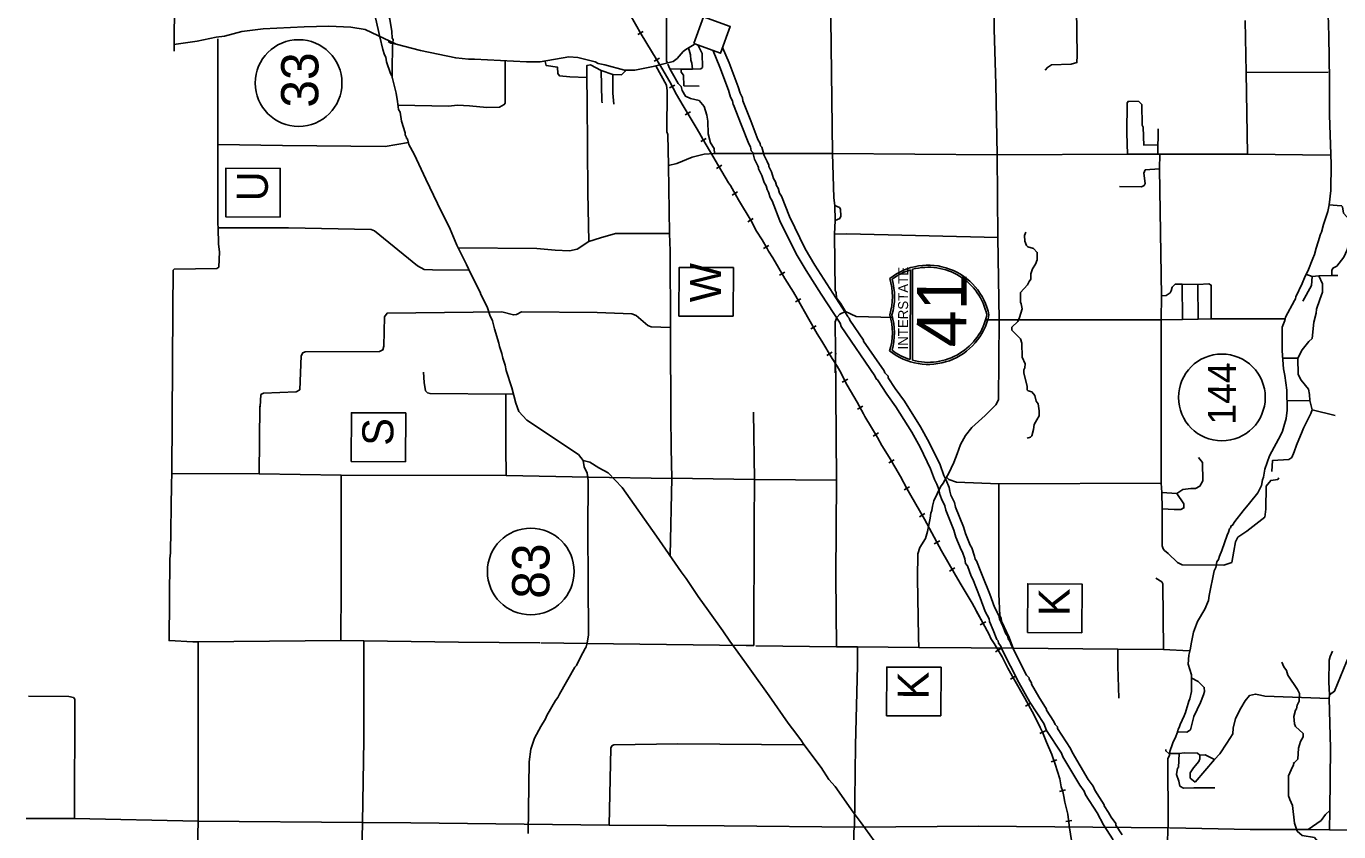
# Model space of a CAD drawing. Extents: x 299354 to 1325680, y 96128 to 228242.
# Drawn here: x 299553 to 341858, y 158651 to 184619 of the extents above; entities that cross this region are included whole.
import ezdxf

# ---------------------------------------------------------------- set-up
doc = ezdxf.new("R2010")
doc.units = 0
for name, color, linetype in [('Level 12', 7, 'Continuous'), ('Level 13', 7, 'Continuous'), ('Level 2', 7, 'Continuous'), ('Level 4', 7, 'Continuous'), ('Level 57', 7, 'Continuous')]:
    doc.layers.add(name, color=color, linetype=linetype)

msp = doc.modelspace()

# ---------------------------------------------------------------- linework, layer by layer
at = {"layer": 'Level 12'}
for p, q in [((308332, 182788), (308332, 182788)), ((328055, 176764), (328047, 173872)), ((328114, 173853), (328122, 176783)), ((338091, 172653), (338091, 172653)), ((315815, 167041), (315815, 167041))]:
    msp.add_line(p, q, dxfattribs=at)
for centre in [(308332, 182788), (338091, 172653), (315815, 167041)]:
    msp.add_circle(centre, 1398, dxfattribs=at)
for centre, radius, start, end in [((328624, 174917), 1999, 11.3832, 128.1773), ((328624, 174917), 1933, 11.7868, 105.0434), ((325474, 175909), 1999, 342.8553, 16.8422), ((325474, 175909), 2066, 343.4192, 15.5586), ((328624, 174917), 1933, 107.1012, 126.8422), ((328626, 175717), 1999, 231.5152, 348.3093), ((325471, 174741), 1999, 342.8502, 16.8372), ((325471, 174741), 2066, 344.1339, 16.2733), ((328626, 175717), 1933, 254.649, 347.9057), ((328626, 175717), 1933, 232.8503, 252.5912)]:
    msp.add_arc(centre, radius, start, end, dxfattribs=at)
at = {"layer": 'Level 13'}
for p, q in [((306839, 179290), (306839, 179290)), ((321447, 176091), (321447, 176091)), ((310886, 171402), (310886, 171402)), ((332686, 165889), (332686, 165889)), ((328138, 163206), (328138, 163206))]:
    msp.add_line(p, q, dxfattribs=at)
for points in [[(307733, 178468), (305983, 178475), (305989, 180045), (307739, 180038)], [(322341, 175269), (320591, 175276), (320598, 176846), (322348, 176839)], [(311779, 170581), (310030, 170588), (310036, 172158), (311786, 172151)], [(333580, 165068), (331830, 165075), (331836, 166645), (333586, 166638)], [(329032, 162384), (327282, 162391), (327288, 163961), (329038, 163954)]]:
    msp.add_lwpolyline(points, close=True, dxfattribs=at)
at = {"layer": 'Level 2'}
for points in [[(310952, 184277), (310809, 184886), (310825, 185331), (310839, 185723), (310854, 186115), (310836, 186444), (310724, 186774), (310602, 187115), (310416, 187509), (310199, 187873), (309795, 188471), (308893, 189723), (308168, 190760), (307672, 191603), (307050, 192523), (306648, 193301), (306143, 194262), (305698, 195020), (304423, 196414)], [(320131, 191177), (320151, 189785), (320164, 187519), (320191, 186852), (320193, 183502), (320223, 183429)], [(336322, 158097), (336363, 158913), (336349, 161013), (336400, 161113), (336417, 161237), (336503, 161487), (336520, 161553), (336588, 161669), (336657, 161860), (336683, 161960), (336717, 162010), (336751, 162109), (336870, 162383), (336921, 162500), (336938, 162566), (337007, 162782), (337025, 162857), (337059, 162940), (337111, 163173), (337116, 163715), (337002, 164057), (337022, 164340), (337073, 164515), (337109, 164765), (337179, 165089), (337307, 165430), (337544, 165827), (337663, 166101), (337682, 166268), (337847, 167066), (337898, 167166), (337933, 167349), (337984, 167432), (338019, 167540), (338087, 167723), (338258, 168213), (338309, 168312), (338335, 168412), (338369, 168445), (338386, 168511), (338436, 168536), (338504, 168652), (338774, 169000), (338985, 169239), (339255, 169579), (339366, 169811), (339401, 169994), (339435, 170085), (339470, 170335), (339625, 170775), (339989, 171447), (340041, 171563), (340092, 171721), (340161, 171971), (340197, 172245), (340186, 172887), (340124, 173363), (340076, 173580), (340031, 174155), (340038, 174922), (340124, 175138), (340141, 175237), (340430, 175777), (340464, 175835), (340473, 175901), (340677, 176324), (340779, 176557), (340864, 176723), (341026, 177130), (341077, 177262), (341129, 177470), (341198, 177670), (341267, 177911), (341301, 177977), (341370, 178226), (341421, 178384), (341507, 178650), (341551, 178866), (341605, 179324), (341613, 180174), (341561, 181750), (341563, 182883), (341543, 184308), (341516, 185000)], [(311475, 184039), (310479, 184518), (310017, 184588), (309302, 184617), (308513, 184605), (307187, 184536), (306502, 184449), (305943, 184297), (305679, 184268), (305057, 184137), (304309, 184030)], [(305728, 184209), (305732, 180807)], [(310952, 184277), (311048, 183868), (311096, 183701), (311146, 183617), (311161, 183467), (311291, 183091), (311340, 183023), (311477, 182464), (311524, 182188), (311555, 181938), (311605, 181854), (311652, 181562), (311765, 181186), (311765, 181119), (311814, 181036), (311814, 181002), (311839, 180985), (311887, 180802), (312051, 180492), (312435, 179688), (312812, 178910), (313213, 178073), (313433, 177563), (313744, 176935), (313883, 176634), (314195, 176022), (314194, 175997), (314358, 175679), (314415, 175545), (314497, 175303), (314578, 175119), (314643, 174860), (314789, 174400), (314804, 174300), (314886, 174066), (314909, 173924), (314990, 173690), (315022, 173523), (315201, 172963), (315329, 172470), (315435, 172194), (315683, 171925), (317349, 170810), (317506, 170617)], [(311217, 184125), (311300, 184074), (311475, 184039), (312265, 183840), (313397, 183596), (313806, 183559), (313997, 183558), (315673, 183476), (315840, 183474), (316115, 183472), (317042, 183630), (317334, 183611), (317891, 183472), (317991, 183422), (318199, 183370), (318840, 183206), (319165, 183203), (319758, 183322), (320402, 183483), (320536, 183582), (320730, 183805), (320814, 183871), (321082, 184035), (321106, 184048)], [(321697, 183825), (321911, 183297), (322189, 182563), (322256, 182338), (322317, 182213), (322337, 182094), (322349, 182081), (322598, 181452), (322839, 180831), (322896, 180729), (322915, 180606), (322971, 180549), (323028, 180333), (323134, 180118), (323158, 180069), (323157, 180027), (323266, 179804), (323333, 179579), (323398, 179472), (323430, 179356), (323480, 179271), (323530, 179100), (323599, 178994), (323848, 178351), (324370, 177284), (324687, 176748), (325174, 175982), (325787, 175044), (325820, 174944), (326909, 173353), (326949, 173252), (326988, 173215), (327290, 172759), (327585, 172349), (328098, 171536), (328364, 171050), (328702, 170351), (328825, 170004), (328908, 169852), (328979, 169662), (328994, 169558), (329051, 169383), (329162, 169155), (329193, 169020), (329447, 168371), (329512, 168152), (329683, 167740), (329730, 167661), (329802, 167445), (329831, 167302), (329889, 167224), (330014, 166895), (330064, 166793), (330305, 166191), (330462, 165757), (330586, 165520), (330601, 165425), (330722, 165150), (330839, 164846), (330878, 164806), (330892, 164732), (330966, 164638), (331009, 164519), (331543, 163464), (331546, 163459), (331905, 162833), (332350, 162137), (332443, 161914), (332919, 161182), (332966, 161068), (333509, 160156), (333651, 159956), (333698, 159842), (334075, 159260), (334272, 158877), (334588, 158388)], [(321999, 183931), (322210, 183439), (322502, 182668), (322564, 182458), (322634, 182316), (322651, 182215), (322906, 181572), (323138, 180972), (323212, 180839), (323224, 180762), (323267, 180718), (323339, 180449), (323430, 180263), (323488, 180144), (323488, 180102), (323575, 179924), (323638, 179714), (323704, 179604), (323737, 179486), (323785, 179403), (323833, 179240), (323895, 179145), (324151, 178483), (324661, 177441), (324968, 176921), (325451, 176161), (326037, 175265), (326037, 175250), (326082, 175204), (326103, 175139), (326539, 174504), (326538, 174471), (326887, 173969), (327203, 173508), (327228, 173443), (327337, 173343), (327336, 173287), (327562, 172946), (327859, 172534), (328382, 171704), (328658, 171202), (329007, 170478), (329128, 170139), (329209, 169990), (329301, 169745), (329317, 169633), (329358, 169507), (329475, 169265), (329509, 169117), (329760, 168478), (329824, 168262), (329979, 167888), (330032, 167799), (330121, 167531), (330140, 167439), (330181, 167383), (330317, 167027), (330365, 166927), (330613, 166309), (330765, 165890), (330903, 165625), (330920, 165519), (331027, 165276), (331122, 165028), (331183, 164966), (331201, 164873), (331258, 164800), (331313, 164651), (331796, 163695), (331876, 163614), (331875, 163565), (331958, 163447), (331957, 163406), (332187, 163004), (332442, 162606), (332442, 162573), (332678, 162208), (332720, 162107), (332795, 162030), (332795, 161978), (333212, 161337), (333262, 161217), (333786, 160336), (333941, 160117), (333992, 159996), (334298, 159523), (334298, 159490), (334440, 159273), (334518, 159120), (334676, 158919), (334676, 158861), (334876, 158551)], [(319842, 183338), (320186, 182718), (320209, 182535), (320197, 181218), (320230, 181126), (320254, 180134)], [(305732, 180807), (305725, 178249), (305741, 178124)], [(320254, 180134), (320284, 177942)], [(304274, 175495), (304285, 176754), (304319, 176787), (305695, 176808), (305762, 176857), (305784, 177349), (305753, 177599), (305741, 178124)], [(320284, 177942), (320312, 177384), (320323, 174909)], [(304274, 175495), (304241, 170196)], [(320323, 174909), (320331, 171861)], [(320330, 172067), (320337, 171017)], [(320337, 171017), (320361, 170050)], [(315727, 158591), (315765, 160908), (315819, 161316), (315930, 161673), (316134, 162046), (316286, 162295), (316337, 162394), (316617, 162883), (316685, 162983), (316736, 163091), (317236, 163961), (317286, 164011), (317422, 164284), (317567, 164558), (317600, 164608), (317635, 164741), (317671, 164991), (317670, 166741), (317652, 168349), (317667, 169974), (317635, 170208), (317537, 170417), (317506, 170617)], [(317506, 170617), (317722, 170565), (318012, 170379), (318311, 170218), (318765, 169747), (319868, 168179), (320659, 167030), (320823, 166812), (321210, 166234), (321539, 165772), (322009, 165126), (322231, 164799), (322346, 164632), (322766, 164053), (322931, 163826), (323499, 163029), (324116, 162157), (324256, 161973), (324520, 161612), (324619, 161461), (325171, 160723), (325426, 160337), (325624, 160110), (326208, 159280), (326463, 158936), (327303, 157778)], [(304183, 167454), (304201, 167638), (304238, 169854), (304241, 170196)], [(304241, 170196), (307060, 170187)], [(307060, 170187), (309704, 170146)], [(309704, 170146), (315024, 170131)], [(315024, 170131), (317691, 170086)], [(317691, 170086), (320364, 170041)], [(320305, 167558), (320361, 170050)], [(304183, 167454), (304158, 164813), (304925, 164773), (305092, 164771)], [(305092, 164771), (305089, 158996)], [(310430, 164806), (310434, 161606), (310393, 158948)], [(310430, 164806), (313482, 164762)], [(313482, 164762), (316109, 164738)], [(316142, 164738), (317621, 164721)], [(317621, 164721), (322755, 164661)], [(322755, 164661), (323005, 164659)], [(323072, 164642), (325665, 164618)], [(325665, 164618), (326349, 164612)], [(326349, 164612), (328325, 164594)], [(328325, 164594), (330010, 164579)], [(330010, 164579), (331361, 164567)], [(331361, 164567), (334738, 164536)], [(334738, 164536), (336214, 164523)], [(336214, 164523), (337040, 164482)], [(341555, 163066), (341723, 163181), (342107, 164128), (342277, 164501)], [(341554, 162949), (341555, 163066)], [(341554, 162949), (341589, 161341), (341571, 159341)], [(340873, 158722), (341293, 159018), (341436, 159209), (341571, 159341)], [(305089, 158996), (305085, 158554), (305033, 156521), (305065, 156454), (305132, 156421), (305949, 156380), (306249, 156344), (306331, 156268), (306305, 151635)], [(310275, 153424), (310393, 158948)], [(336408, 158773), (339005, 158722)], [(339005, 158722), (339155, 158721)], [(339155, 158721), (340873, 158722)]]:
    msp.add_lwpolyline(points, dxfattribs=at)
msp.add_lwpolyline([(321066, 184064), (321929, 183746), (322247, 184609), (321384, 184927)], close=True, dxfattribs=at)
at = {"layer": 'Level 4'}
for p, q in [((319267, 184348), (319440, 184447)), ((319789, 183491), (319959, 183595)), ((320285, 182631), (320462, 182724)), ((320788, 181761), (320960, 181863)), ((336042, 181315), (336024, 180502)), ((321295, 180900), (321468, 181001)), ((335579, 180792), (336036, 180782)), ((321801, 180037), (321973, 180138)), ((322309, 179177), (322482, 179276)), ((322816, 178314), (322988, 178416)), ((323319, 177452), (323493, 177550)), ((323829, 176590), (324001, 176691)), ((324345, 175735), (324519, 175834)), ((324840, 174866), (325014, 174965)), ((325355, 174007), (325527, 174110)), ((325854, 173148), (326032, 173240)), ((326342, 172273), (326518, 172369)), ((326846, 171405), (327018, 171507)), ((327355, 170545), (327527, 170646)), ((327845, 169678), (328022, 169772)), ((328343, 168808), (328517, 168907)), ((328821, 167932), (328997, 168027)), ((329310, 167057), (329484, 167156)), ((330304, 165323), (330478, 165420)), ((330798, 164452), (330970, 164554)), ((331275, 163575), (331448, 163675)), ((331763, 162704), (331938, 162801)), ((332220, 161822), (332401, 161908)), ((332587, 160903), (332775, 160970)), ((332856, 159945), (333046, 160006)), ((333058, 158986), (333256, 159011))]:
    msp.add_line(p, q, dxfattribs=at)
for points in [[(332400, 183208), (332468, 183290), (332602, 183373), (333236, 183400), (333420, 183449), (333422, 183674), (333374, 187466), (333348, 188291), (333338, 190833), (333306, 191850), (333322, 193583), (333308, 195733)], [(330637, 190999), (330668, 190657), (330669, 189032), (330689, 188473), (330694, 187148), (330745, 185506), (330753, 184523), (330803, 182747), (330849, 180472)], [(311348, 182957), (311351, 183223), (311357, 183973), (311376, 184190), (311352, 184240), (311337, 184448), (311274, 184849), (311177, 185192), (311065, 185684), (310999, 185852), (310966, 185877), (310983, 185885), (310967, 185919), (310934, 185960), (315387, 185954), (316421, 185911)], [(325479, 185735), (325545, 180520)], [(320508, 182422), (320296, 182826), (320041, 183270), (319376, 184359), (319006, 185004), (318826, 185356)], [(304317, 183812), (304322, 184320), (304334, 185059)], [(329660, 166660), (329457, 167001), (329056, 167706), (328505, 168726), (328070, 169488), (327939, 169714), (327734, 170100), (327365, 170724), (327135, 171105), (326987, 171365), (326798, 171683), (326584, 172043), (326535, 172127), (326330, 172504), (326018, 173049), (325781, 173509), (325688, 173659), (325534, 173903), (325197, 174464), (325049, 174699), (324779, 175177), (324401, 175838), (324278, 176048), (324007, 176485), (323613, 177154), (323481, 177372), (323432, 177455), (323276, 177732), (323095, 178017), (322915, 178343), (322512, 179022), (322250, 179483), (322190, 179571), (321363, 180983), (321248, 181175), (321141, 181360), (320730, 182055), (320508, 182422), (320296, 182826), (320041, 183270), (319376, 184359), (319006, 185004)], [(338837, 184808), (338871, 183133)], [(320898, 183920), (320962, 183695), (320978, 183528), (321010, 183428), (321025, 183236)], [(321025, 183236), (321300, 183250), (321351, 183291), (321338, 183741), (321200, 184015)], [(311540, 182072), (313166, 182040), (313458, 182071), (313842, 182051), (314400, 181996), (314809, 182009), (314960, 182091), (314985, 182140), (314989, 183515)], [(316282, 183487), (316314, 183353), (316672, 183300), (316687, 183092), (316736, 183025), (317078, 182988), (317620, 182967)], [(317620, 182967), (317623, 183358), (317740, 183374), (318089, 183196)], [(318089, 183196), (318105, 182212), (318121, 182145)], [(318089, 183196), (318463, 183059)], [(318463, 183059), (318738, 183056), (318856, 183172), (318873, 183205)], [(320236, 183398), (320299, 183242)], [(320299, 183242), (320381, 183092), (320562, 182773), (320661, 182681)], [(320299, 183242), (320666, 183239)], [(320666, 183239), (320665, 183139), (320740, 183038), (320753, 182697)], [(320666, 183239), (321025, 183236)], [(317620, 182967), (317629, 182183)], [(318463, 183059), (318457, 182467), (318488, 182109)], [(338871, 183133), (341515, 183142)], [(338871, 183133), (338914, 180490)], [(322190, 179571), (321363, 180983), (321248, 181175), (321141, 181360), (320730, 182055), (320508, 182422)], [(320661, 182681), (320693, 182547), (320800, 182363), (320966, 182295), (321241, 182225), (321406, 182032), (321487, 181748), (321518, 181556), (321531, 181148), (321612, 180864), (321727, 180679), (321742, 180521)], [(320753, 182697), (321245, 182692)], [(317629, 182183), (317652, 179258), (317688, 177682)], [(335052, 180500), (335025, 181167), (335034, 182151), (335085, 182200), (335410, 182197), (335509, 182096), (335520, 181429), (335552, 181363), (335580, 180771)], [(305732, 180807), (307817, 180772), (311119, 180742), (311871, 180869)], [(320254, 180134), (320522, 180199), (321015, 180394), (321408, 180491), (321742, 180521)], [(321742, 180521), (325545, 180520)], [(325545, 180520), (325582, 179086), (325613, 178844)], [(325545, 180520), (330849, 180472)], [(330849, 180472), (335052, 180500)], [(330849, 180472), (330874, 177813)], [(335052, 180500), (336086, 180491)], [(336082, 180024), (336086, 180491)], [(336086, 180491), (338914, 180490)], [(338914, 180490), (341582, 180466)], [(334793, 179453), (335501, 179446), (335585, 179487), (335619, 179554), (335572, 179887), (335623, 179987), (336082, 180024)], [(336082, 180024), (336144, 175924)], [(324007, 176485), (323613, 177154), (323481, 177372), (323432, 177455), (323276, 177732), (323095, 178017), (322915, 178343), (322512, 179022), (322250, 179483), (322190, 179571)], [(325613, 178844), (325625, 178352)], [(325613, 178844), (325763, 178776), (325795, 178726), (325810, 178501), (325776, 178418), (325625, 178352)], [(341534, 178867), (341951, 178830), (341984, 178796), (342015, 178596), (342222, 178352), (342503, 178083)], [(305741, 178124), (308009, 178120), (310669, 178063), (310777, 178028), (312168, 176899), (312375, 176781), (312642, 176761), (313843, 176751)], [(325604, 177911), (325625, 178352)], [(313483, 177479), (316009, 177456), (316601, 177401), (317059, 177380), (317310, 177428), (317688, 177682)], [(317688, 177682), (318064, 177796), (318549, 177941), (320284, 177942)], [(325604, 177911), (325997, 177924), (330874, 177813)], [(325604, 177911), (325621, 176102), (325654, 176035), (325669, 175860), (325801, 175692), (325957, 175424)], [(330874, 177813), (330917, 175154)], [(341630, 176582), (341631, 176749), (341665, 176815), (341799, 176889), (342019, 177171), (342129, 177411), (342250, 177852), (342503, 178083)], [(325688, 173659), (325534, 173903), (325197, 174464), (325049, 174699), (324779, 175177), (324401, 175838), (324278, 176048), (324007, 176485)], [(340538, 173917), (340674, 174183), (340893, 174456), (341002, 174555), (341057, 175079), (341127, 175370), (341144, 175503), (341247, 175811), (341333, 176043), (341335, 176318), (341221, 176569)], [(340705, 175757), (340976, 176263), (341004, 176555)], [(340796, 176623), (341004, 176555)], [(341004, 176555), (341221, 176569)], [(341221, 176569), (341630, 176582)], [(341630, 176582), (341830, 176581)], [(336144, 175924), (336295, 175939), (336421, 176021), (336454, 176088), (336489, 176204), (336590, 176303), (336815, 176301)], [(336815, 176301), (336821, 175168)], [(336815, 176301), (337315, 176296)], [(337315, 176296), (337674, 176310), (337741, 176276), (337747, 175192)], [(337315, 176296), (337322, 175180)], [(336137, 175157), (336144, 175924)], [(307060, 170187), (307080, 172370), (307097, 172353), (307117, 172745), (307201, 172794), (308252, 172834), (308370, 172900), (308413, 173991), (308464, 174091), (308548, 174123), (310941, 174135), (311042, 174184), (311076, 174301), (311102, 175250), (311186, 175366), (314881, 175416), (315256, 175313), (315356, 175328), (315515, 175410), (317950, 175388), (319067, 175345), (319209, 175294), (319589, 174973), (319697, 174931), (320323, 174909)], [(325652, 174052), (325636, 174119), (325628, 175085), (325680, 175235), (325781, 175334), (325957, 175424)], [(325957, 175424), (326306, 175263), (327493, 175228)], [(329210, 170086), (329278, 170194), (329448, 170559), (329559, 170833), (329662, 171132), (329831, 171422), (330026, 171687), (330463, 172075), (330808, 172414), (330893, 172579), (330917, 175154)], [(330448, 175159), (330917, 175154)], [(330917, 175154), (336137, 175157)], [(336137, 175157), (336821, 175168)], [(336137, 175157), (336139, 169890)], [(336821, 175168), (337322, 175180)], [(337322, 175180), (337747, 175192)], [(337747, 175192), (340107, 175188)], [(325630, 173444), (325635, 174204), (325665, 169985)], [(340029, 173922), (340538, 173917)], [(340538, 173917), (340550, 173392), (340648, 173208), (340879, 172914), (340911, 172747), (340925, 172555)], [(312361, 173464), (312375, 173139), (312422, 172863), (312489, 172796), (312572, 172779), (315015, 172757)], [(327365, 170724), (327135, 171105), (326987, 171365), (326798, 171683), (326584, 172043), (326535, 172127), (326330, 172504), (326018, 173049), (325781, 173509), (325688, 173659)], [(315015, 172757), (315249, 172771)], [(315015, 172757), (315016, 171031), (315024, 170131)], [(339703, 170266), (339723, 170624), (340249, 170653), (340350, 170719), (340426, 170901), (340495, 171109), (340683, 171557), (340717, 171665), (340963, 172130), (340998, 172255)], [(340183, 172545), (340925, 172555)], [(340925, 172555), (340998, 172255)], [(340998, 172255), (341738, 172073)], [(322991, 172176), (323021, 170009)], [(329056, 167706), (328505, 168726), (328070, 169488), (327939, 169714), (327734, 170100), (327365, 170724)], [(336644, 169561), (336837, 169684), (337088, 169715), (337238, 169714), (337381, 169796), (337482, 169961), (337471, 170553), (337339, 170713)], [(309704, 170146), (309704, 169060)], [(328279, 166826), (328287, 167611), (328355, 167811), (328533, 168101), (328602, 168333), (328689, 168758), (328707, 168924), (328741, 169007), (328759, 169149), (328811, 169315), (329024, 169771), (329108, 169887), (329210, 170086)], [(329210, 170086), (329293, 170002), (329534, 169917), (330901, 169871)], [(320361, 170050), (323021, 170009)], [(323021, 170009), (323017, 168567)], [(323021, 170009), (325665, 169985)], [(325665, 169985), (325648, 166884)], [(330901, 169871), (336139, 169890)], [(330901, 169871), (330902, 166313), (330929, 165621), (330978, 165537), (330985, 165445), (331231, 164918), (331361, 164567)], [(336139, 169890), (336153, 169590)], [(339473, 168793), (339509, 169051), (339516, 169793), (339667, 169975), (339893, 170006), (339927, 170064)], [(336153, 169590), (336164, 169057)], [(336153, 169590), (336644, 169561)], [(336164, 169057), (336556, 169036), (336765, 169035), (336865, 169092), (336867, 169225), (336644, 169561)], [(309704, 169060), (309704, 166554), (309688, 164813)], [(336164, 169057), (336170, 167873), (336203, 167773), (336244, 167723), (336360, 167621), (336657, 167327), (336815, 167259), (338149, 167247), (338409, 167328)], [(323017, 168567), (323005, 164659)], [(338531, 167993), (338600, 168143), (338893, 168340), (339473, 168793)], [(338409, 167328), (338479, 167702), (338531, 167993)], [(329457, 167001), (329056, 167706)], [(325648, 166884), (325665, 164618)], [(328325, 164594), (328312, 164928), (328279, 166826)], [(330649, 164886), (330589, 165015), (330384, 165384), (330040, 166020), (329687, 166615), (329457, 167001)], [(335960, 166825), (336159, 166707), (336192, 166640), (336214, 164523)], [(333239, 158366), (333184, 158781), (333130, 159217), (333033, 159601), (332993, 159793), (332961, 159944), (332913, 160094), (332865, 160353), (332719, 160829), (332605, 161147), (332434, 161540), (332311, 161863), (332238, 162017), (332042, 162410), (331738, 162955), (331385, 163583), (331188, 163927), (331008, 164295), (330754, 164722), (330649, 164886), (330589, 165015), (330384, 165384), (330174, 165772)], [(305092, 164771), (309688, 164813)], [(309688, 164813), (310430, 164806)], [(326286, 161446), (326343, 164004), (326349, 164612)], [(332311, 161863), (332238, 162017), (332042, 162410), (331738, 162955), (331385, 163583), (331188, 163927), (331008, 164295), (330754, 164722), (330649, 164886)], [(334738, 164536), (334733, 163994), (334774, 162961)], [(341542, 163474), (341549, 164183), (341583, 164299), (341651, 164473)], [(336640, 161877), (336965, 161858), (337083, 161940), (337187, 162364), (337400, 162820), (337502, 163069), (337536, 163169), (337521, 163303), (337322, 163496), (337098, 163615)], [(341542, 163474), (341555, 163066)], [(299624, 163021), (300923, 163009), (301072, 162974), (301122, 162924), (301103, 159082)], [(337858, 160983), (338026, 161165), (338255, 161504), (338441, 161811), (338459, 161994), (338529, 162302), (338699, 162633), (338843, 162874), (338978, 163039), (339178, 163088), (339337, 163053), (339470, 163018)], [(339470, 163018), (341554, 162949)], [(332913, 160094), (332865, 160353), (332719, 160829), (332605, 161147), (332434, 161540), (332311, 161863)], [(318340, 158859), (318396, 161342), (318430, 161417), (318489, 161450), (320557, 161481), (324604, 161456)], [(326245, 158804), (326286, 161446)], [(336285, 161305), (336284, 161255), (336384, 161179), (336709, 161176)], [(336709, 161176), (336876, 161192), (337301, 161188), (337384, 161120)], [(336709, 161176), (336688, 160727), (336663, 160702), (336628, 160502), (336701, 160285), (336732, 160126), (336849, 160059), (337191, 160072)], [(337226, 160247), (337068, 160382), (337070, 160548), (337172, 160714), (337349, 160921), (337383, 161004), (337384, 161120)], [(337226, 160247), (337858, 160983)], [(337384, 161120), (337551, 161136), (337858, 160983)], [(333184, 158781), (333130, 159217), (333033, 159601), (332993, 159793), (332961, 159944), (332913, 160094)], [(337191, 160072), (337866, 160066)], [(299553, 159074), (301103, 159082)], [(301103, 159082), (305089, 158996)], [(341565, 158716), (341571, 159341)], [(305089, 158996), (310393, 158948)], [(310393, 158948), (311952, 158934), (318340, 158859)], [(318340, 158859), (322051, 158842)], [(322051, 158842), (326245, 158804)], [(326196, 156147), (326228, 158680), (326245, 158804)], [(326245, 158804), (330246, 158831)], [(330246, 158831), (336388, 158773)], [(333459, 155181), (333387, 156381), (333357, 156707), (333313, 157349), (333252, 157974), (333239, 158366), (333184, 158781)], [(340873, 158722), (341565, 158716)], [(341565, 158716), (344192, 158675)]]:
    msp.add_lwpolyline(points, dxfattribs=at)
at = {"layer": 'Level 57'}
for points in [[(331702, 173422), (331703, 173539), (331737, 173605), (331755, 173738), (331657, 173948), (331644, 174406), (331596, 174540), (331323, 174826), (331324, 174917), (331509, 175099), (331569, 175232), (331655, 175506), (331623, 175673), (331598, 175723), (331601, 176031), (331828, 176279), (331880, 176387), (331930, 176470), (331932, 176637), (331983, 176803), (332085, 176944), (332136, 177093), (332138, 177327), (332023, 177453), (331840, 177504), (331790, 177555), (331741, 177689), (331726, 177872), (331777, 177980)], [(331818, 171341), (331917, 171370), (331967, 171420), (332019, 171619), (332037, 171777), (332130, 171927), (332198, 172059), (332200, 172218), (332168, 172451), (332103, 172535), (332062, 172719), (331963, 172828), (331847, 172863), (331814, 172896), (331815, 173013), (331702, 173437)], [(340023, 164113), (340088, 163963), (340170, 163845), (340219, 163703), (340523, 163242), (340589, 163108), (340587, 162858), (340519, 162734), (340501, 162617), (340467, 162568), (340415, 162368), (340430, 162126), (340462, 162043), (340710, 161824), (340709, 161715), (340625, 161566), (340556, 161350), (340536, 160992), (340418, 160868)], [(340418, 160868), (340401, 160826), (340401, 160810), (340324, 160652), (340239, 160453), (340233, 159811), (340282, 159694), (340372, 159502), (340434, 158926), (340515, 158675), (340680, 158532), (341071, 158462), (341170, 158344), (341302, 158143), (341476, 157967), (341932, 157729), (342280, 157434), (342378, 157217), (342486, 157199), (343031, 157553), (343366, 157633), (343575, 157748), (344035, 157860), (344436, 157973)], [(340385, 160860), (340418, 160868)]]:
    msp.add_lwpolyline(points, dxfattribs=at)

# ---------------------------------------------------------------- texts
at = {"layer": 'Level 12'}
for s, height, rotation, p in [('33', 1200, 89.767, (308965, 181992)), ('INTERSTATE', 319.9, 89.8462, (327973, 174198)), ('41', 1599.6, 89.8462, (329856, 174266)), ('144', 900, 89.767, (338537, 171773)), ('83', 1200, 89.767, (316412, 166160))]:
    msp.add_text(s, height=height, rotation=rotation, dxfattribs=at).set_placement(p)
at = {"layer": 'Level 13'}
for s, p in [('U', (307338, 178973)), ('W', (321946, 175718)), ('S', (311384, 171093)), ('K', (333185, 165604)), ('K', (328637, 162920))]:
    msp.add_text(s, height=1000, rotation=89.767, dxfattribs=at).set_placement(p)

doc.saveas('drawing.dxf')
